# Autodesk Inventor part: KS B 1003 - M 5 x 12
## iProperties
IsCustomPart: 0
Created: 2009-02
Part Number: KS B 1003 - M 5 x 12
Material: 강, 연강
Description: 6각머리 태핑 나사
Document SubType Name: Modeling
Standard: KS B 1003
Designer: KYOUNG IL JANG
Standards Organization: KS
Language: ko-KR
Size Designation: M 5 x 12
Categories: <MemberInstance><Categories><Category DisplayName="조임쇠" InternalName="e4da775c-781d-43d5-af7c-5136215cf5a6" Mnemonic="FSTN"><Category DisplayName="볼트" InternalN
Density: 1 g/cm^3
Author: KYOUNG IL JANG
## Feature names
1. Fillet2
